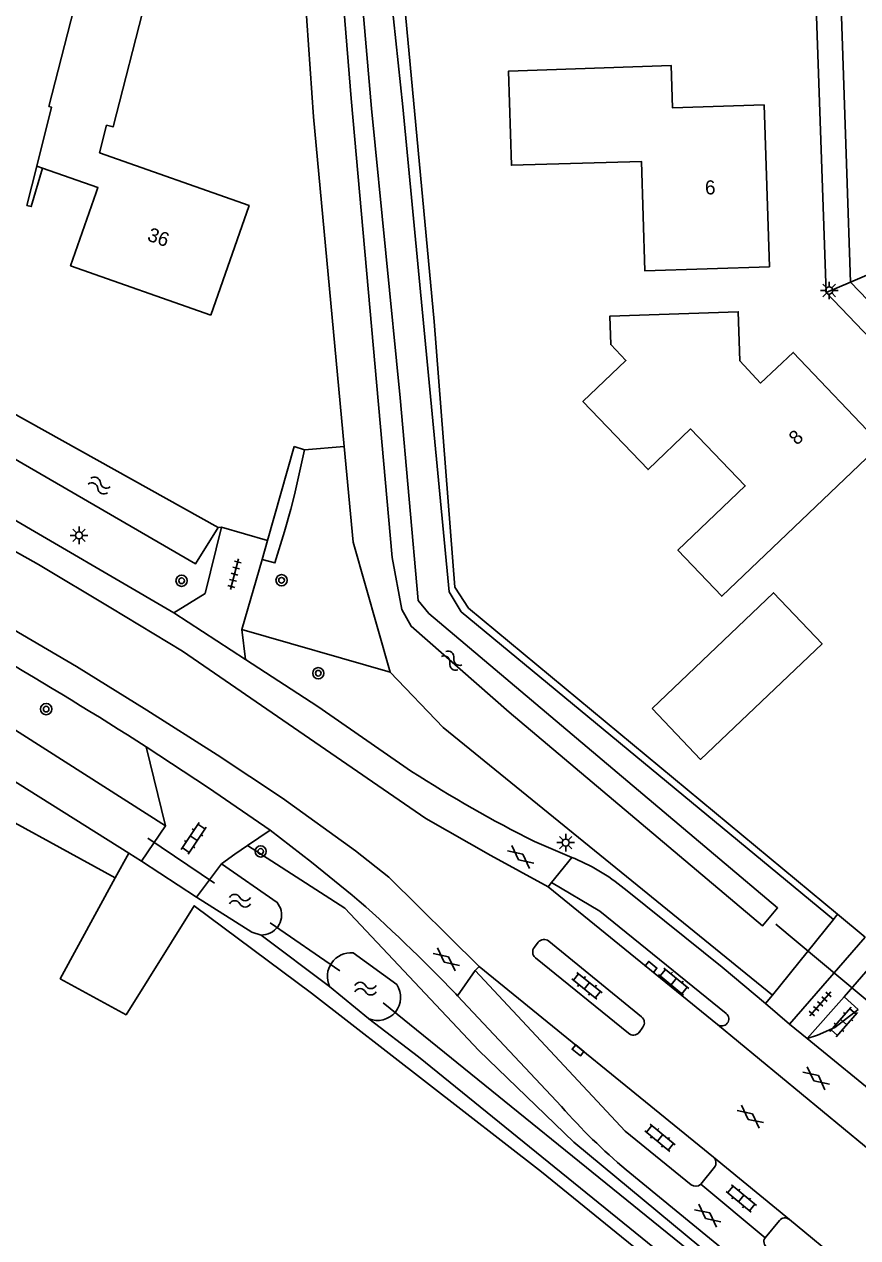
# Model space of a CAD drawing. Extents: x 136000 to 141014, y 402000 to 403500.
# Drawn here: x 137059.9 to 137119.1, y 402057.2 to 402143.4 of the extents above; entities that cross this region are included whole.
import ezdxf

# ---------------------------------------------------------------- set-up
doc = ezdxf.new("R2010")
doc.units = 0
for name, color, linetype in [('gg-afsc-erfafscheiding', 7, 'Continuous'), ('gg-afsc-muur', 7, 'Continuous'), ('gg-anno-huisnummerreeks BGT', 7, 'Continuous'), ('gg-bbg-bijgebouw', 7, 'Continuous'), ('gg-bbg-gedigitaliseerde bebouwing', 7, 'Continuous'), ('gg-bbg-hoofdgebouw', 7, 'Continuous'), ('gg-knt-bronhoudergrens', 7, 'Continuous'), ('gg-knt-verharding', 7, 'Continuous'), ('gg-knt-verharding nz', 7, 'Continuous'), ('gg-kntw-bovenkant insteek waterloop', 7, 'Continuous'), ('gg-kntw-waterlijn', 7, 'Continuous'), ('gg-kwrk-duiker nz buis', 7, 'Continuous'), ('gt-grn-groengrens', 7, 'Continuous'), ('gt-grn-groengrens NZ', 7, 'Continuous'), ('gt-grn-vlakafsluiter', 7, 'Continuous'), ('gt-grn-weggrens', 7, 'Continuous'), ('gt-symb-boom', 7, 'Continuous'), ('gt-symb-gesloten verharding', 7, 'Continuous'), ('gt-symb-klinker verharding', 7, 'Continuous'), ('gt-symb-kolk', 7, 'Continuous'), ('gt-symb-lichtmast', 7, 'Continuous'), ('gt-symb-tegel verharding', 7, 'Continuous'), ('gt-symb-watersymbool', 7, 'Continuous')]:
    doc.layers.add(name, color=color, linetype=linetype)

# ---------------------------------------------------------------- blocks, each defined once
blk = doc.blocks.new('gt0-KL1')
at = {"layer": 'gt-symb-klinker verharding'}
for p, q in [((-1.15, 0.3), (1.15, 0.3)), ((-1, -0.3), (-1, 0.3)), ((-0.5, 0.3), (-0.5, 0.45)), ((0, -0.3), (0, 0.3)), ((0.5, 0.3), (0.5, 0.45)), ((1, -0.3), (1, 0.3)), ((-1.15, -0.3), (1.15, -0.3)), ((-0.5, -0.45), (-0.5, -0.3)), ((0.5, -0.45), (0.5, -0.3))]:
    blk.add_line(p, q, dxfattribs=at)
blk = doc.blocks.new('gt0-KOLK')
at = {"layer": 'gt-symb-kolk'}
blk.add_lwpolyline([(0, 0), (0.375, 0), (0.375, 0.4), (-0.375, 0.4), (-0.375, 0), (0, 0)], dxfattribs=at)
blk = doc.blocks.new('gt0-LMAST')
at = {"layer": 'gt-symb-lichtmast'}
for p, q in [((-0.182, 0.173), (-0.447, 0.438)), ((-0.005, 0.246), (-0.005, 0.621)), ((0.172, 0.173), (0.437, 0.438)), ((-0.255, -0.004), (-0.63, -0.004)), ((-0.182, -0.181), (-0.447, -0.446)), ((-0.005, -0.254), (-0.005, -0.629)), ((0.437, -0.446), (0.172, -0.181)), ((0.245, -0.004), (0.62, -0.004))]:
    blk.add_line(p, q, dxfattribs=at)
blk.add_circle((-0.005, -0.004), 0.25, dxfattribs=at)
blk = doc.blocks.new('gt0-TEG1')
at = {"layer": 'gt-symb-tegel verharding'}
for p, q in [((-1.125, 0), (1.125, 0)), ((-0.9, -0.25), (-0.9, 0.25)), ((-0.45, -0.25), (-0.45, 0.25)), ((0, -0.25), (0, 0.25)), ((0.45, -0.25), (0.45, 0.25)), ((0.9, -0.25), (0.9, 0.25))]:
    blk.add_line(p, q, dxfattribs=at)
blk = doc.blocks.new('gt0-BOOM')
at = {"layer": 'gt-symb-boom'}
for radius in [0.4, 0.2]:
    blk.add_circle((0, 0), radius, dxfattribs=at)
blk = doc.blocks.new('gt0-WA')
at = {"layer": 'gt-symb-watersymbool'}
for centre, start, end in [((-0.323, 0.022), 28.07249, 151.92751), ((0.427, 0.422), 208.07248, 331.92751), ((-0.323, -0.428), 28.07249, 151.92751), ((0.427, -0.028), 208.07248, 331.92751)]:
    blk.add_arc(centre, 0.425, start, end, dxfattribs=at)
blk = doc.blocks.new('gt0-GESVH1')
at = {"layer": 'gt-symb-gesloten verharding'}
for p, q in [((-0.992, -0.261), (0.008, 0.239)), ((0.008, -0.261), (-0.992, 0.239)), ((0.008, 0.239), (1.008, -0.261)), ((1.008, 0.239), (0.008, -0.261))]:
    blk.add_line(p, q, dxfattribs=at)

msp = doc.modelspace()

# ---------------------------------------------------------------- linework, layer by layer
at = {"layer": 'gg-afsc-erfafscheiding'}
msp.add_line((137072.1, 402081.41), (137068.194, 402083.954), dxfattribs=at)
at = {"layer": 'gg-afsc-muur'}
msp.add_lwpolyline([(137060.741, 402133.32), (137060.044, 402130.545), (137060.348, 402130.457), (137061.137, 402133.182)], dxfattribs=at)
at = {"layer": 'gg-bbg-bijgebouw'}
msp.add_lwpolyline([(137104.457, 402094.809), (137107.903, 402091.187), (137116.545, 402099.408), (137113.098, 402103.03), (137104.457, 402094.809)], dxfattribs=at)
at = {"layer": 'gg-bbg-gedigitaliseerde bebouwing'}
msp.add_lwpolyline([(137073.1, 402122.75), (137075.828, 402130.525), (137065.203, 402134.277), (137065.704, 402136.235), (137066.164, 402136.117), (137068.455, 402145.062), (137063.823, 402146.248), (137061.598, 402137.561)], dxfattribs=at)
at = {"layer": 'gg-bbg-hoofdgebouw'}
msp.add_line((137061.137, 402133.182), (137060.741, 402133.32), dxfattribs=at)
for points in [[(137112.793, 402126.178), (137103.944, 402125.897), (137103.708, 402133.672), (137094.469, 402133.391), (137094.27, 402140.082), (137105.824, 402140.469), (137105.922, 402137.47), (137112.418, 402137.684), (137112.793, 402126.178)], [(137061.598, 402137.561), (137061.793, 402137.512), (137060.741, 402133.32)], [(137061.137, 402133.182), (137065.088, 402131.808), (137064.964, 402131.452)], [(137073.1, 402122.75), (137063.14, 402126.25), (137064.964, 402131.452)], [(137120.71, 402113.567), (137114.495, 402120.096), (137112.169, 402117.924), (137110.7, 402119.498), (137110.58, 402122.986), (137101.46, 402122.685), (137101.524, 402120.656), (137102.597, 402119.529), (137099.547, 402116.614), (137104.172, 402111.774), (137107.2, 402114.668), (137111.078, 402110.611), (137106.296, 402106.041), (137109.412, 402102.781), (137120.71, 402113.567)]]:
    msp.add_lwpolyline(points, dxfattribs=at)
at = {"layer": 'gg-knt-bronhoudergrens'}
msp.add_line((137066.322, 402082.767), (137067.284, 402084.525), dxfattribs=at)
for points in [[(137031.735, 402101.682), (137055.221, 402088.838), (137066.322, 402082.767)], [(137066.322, 402082.767), (137062.407, 402075.608), (137067.085, 402073.05), (137071.929, 402080.799), (137080.27, 402074.591), (137096.604, 402061.892), (137120.347, 402042.619), (137142.522, 402024.619), (137156.112, 402013.588)]]:
    msp.add_lwpolyline(points, dxfattribs=at)
at = {"layer": 'gg-knt-verharding'}
for p, q in [((137115.112, 402175.269), (137116.194, 402142.603)), ((137116.834, 402124.346), (137116.194, 402142.603)), ((137138.099, 402102.093), (137116.834, 402124.346)), ((137077.134, 402106.748), (137079.028, 402113.41)), ((137055.253, 402110.477), (137070.475, 402101.603)), ((137073.869, 402107.676), (137077.134, 402106.748)), ((137076.745, 402105.38), (137077.134, 402106.748)), ((137076.745, 402105.38), (137075.313, 402100.422)), ((137075.565, 402098.277), (137070.475, 402101.603)), ((137140.928, 402100.63), (137118.098, 402074.332)), ((137075.313, 402100.422), (137075.565, 402098.277)), ((137069.883, 402086.481), (137068.503, 402092.08)), ((137077.316, 402086.156), (137075.717, 402085.07)), ((137096.108, 402085.347), (137098.751, 402084.231)), ((137098.751, 402084.231), (137098.965, 402084.141)), ((137097.318, 402082.452), (137097.066, 402082.135)), ((137097.066, 402082.135), (137109.101, 402072.366)), ((137096.099, 402077.849), (137096.373, 402078.205)), ((137097.117, 402078.287), (137103.715, 402072.901)), ((137119.598, 402078.571), (137114.237, 402072.392)), ((137092.179, 402076.49), (137091.881, 402076.184)), ((137108.821, 402062.944), (137092.179, 402076.49)), ((137102.786, 402071.734), (137096.168, 402077.105)), ((137090.638, 402074.401), (137090.519, 402074.528)), ((137098.028, 402066.527), (137090.638, 402074.401)), ((137112.511, 402073.846), (137114.237, 402072.392)), ((137115.482, 402071.362), (137118.098, 402074.332)), ((137118.098, 402074.332), (137119.109, 402073.428)), ((137103.808, 402072.163), (137103.536, 402071.803)), ((137109.101, 402072.366), (137123.63, 402060.371)), ((137114.237, 402072.392), (137115.482, 402071.362)), ((137115.482, 402071.362), (137121.543, 402066.393)), ((137108.821, 402062.944), (137114.219, 402058.512)), ((137115.5, 402051.483), (137102.613, 402062.042)), ((137107.915, 402061.015), (137108.905, 402062.218)), ((137112.487, 402057.213), (137107.915, 402061.015)), ((137113.516, 402058.446), (137112.487, 402057.213)), ((137130.8, 402044.838), (137114.219, 402058.512))]:
    msp.add_line(p, q, dxfattribs=at)
for points in [[(137070.475, 402101.603), (137072.701, 402102.979), (137073.869, 402107.676)], [(137075.565, 402098.277), (137080.723, 402094.955), (137087.369, 402090.332)], [(137077.316, 402086.156), (137072.939, 402089.162), (137068.503, 402092.08)], [(137083.162, 402081.551), (137080.262, 402083.883), (137077.316, 402086.156)], [(137075.717, 402085.07), (137074.805, 402084.451), (137073.878, 402083.778)], [(137097.318, 402082.452), (137100.75, 402080.415), (137109.728, 402073.146)], [(137102.697, 402081.847), (137109.446, 402076.427), (137112.511, 402073.846)], [(137091.881, 402076.184), (137102.559, 402064.78), (137107.227, 402060.976)]]:
    msp.add_lwpolyline(points, dxfattribs=at)
for centre, radius, start, end in [((136923.585, 401866.961), 267.731, 57.22892, 62.60105), ((137139.821, 402172.131), 97.171, 237.33076, 243.26565), ((137093.37, 402070.856), 14.415, 49.6816, 67.16166), ((137008.924, 401996.418), 112.955, 43.75011, 48.91099), ((137096.789, 402077.843), 0.552, 53.60925, 138.96969), ((137096.503, 402077.511), 0.527, 140.12386, 230.47327), ((137103.374, 402072.483), 0.539, 323.5589, 50.80578), ((137109.414, 402072.756), 0.5, 231.28662, 51.12552), ((137103.127, 402072.134), 0.526, 229.49155, 321.02128), ((137130.735, 402095.377), 43.613, 221.41485, 229.84851), ((137108.426, 402062.53), 0.572, 326.88571, 46.31412), ((137107.549, 402061.392), 0.525, 232.26644, 314.22236), ((137113.902, 402058.112), 0.511, 51.61479, 139.11201), ((137112.865, 402056.947), 0.462, 144.80281, 242.75134)]:
    msp.add_arc(centre, radius, start, end, dxfattribs=at)
at = {"layer": 'gg-knt-verharding nz'}
for p, q in [((137116.373, 402190.816), (137118.295, 402132.805)), ((137118.557, 402125.097), (137118.295, 402132.805)), ((137139.381, 402103.29), (137118.557, 402125.097))]:
    msp.add_line(p, q, dxfattribs=at)
for points in [[(137097.066, 402082.135), (137092.995, 402084.357), (137088.379, 402086.999), (137071.101, 402098.883), (137066.007, 402101.968), (137060.875, 402105.046), (137055.665, 402107.95), (137050.439, 402110.718), (137045.082, 402113.527), (137039.711, 402116.175), (137034.31, 402118.696), (137028.848, 402121.106), (137023.353, 402123.566), (137017.776, 402125.868), (137012.197, 402128.034), (137006.579, 402130.096), (137000.948, 402131.975), (136995.13, 402133.791), (136988.319, 402135.892), (136981.107, 402138.306)], [(136979.307, 402130.822), (136984.991, 402129.932), (136990.74, 402128.77), (136996.608, 402127.506), (137002.43, 402126.095), (137008.065, 402124.337), (137013.737, 402122.302), (137019.174, 402119.966), (137031.98, 402114.287), (137037.355, 402111.802), (137042.716, 402109.155), (137053.239, 402103.703), (137058.359, 402100.844), (137063.569, 402097.781), (137068.573, 402094.689), (137073.558, 402091.505), (137078.199, 402088.443), (137083.387, 402084.706), (137085.753, 402082.83), (137092.179, 402076.49)]]:
    msp.add_lwpolyline(points, dxfattribs=at)
at = {"layer": 'gg-kntw-bovenkant insteek waterloop'}
for p, q in [((137079.409, 402151.337), (137080.4, 402136.83)), ((137085.209, 402152.148), (137086.76, 402137.54)), ((137080.4, 402136.83), (137082.584, 402113.423)), ((137058.856, 402115.897), (137073.636, 402107.672)), ((137068.194, 402083.954), (137069.883, 402086.481)), ((137067.284, 402084.525), (137068.194, 402083.954)), ((137073.878, 402083.778), (137072.1, 402081.41)), ((137113.02, 402074.45), (137117.34, 402079.81)), ((137086.319, 402075.19), (137083.217, 402077.455))]:
    msp.add_line(p, q, dxfattribs=at)
for points in [[(137117.34, 402079.81), (137090.89, 402101.68), (137090.05, 402103.1), (137086.76, 402137.54)], [(137073.636, 402107.672), (137072.013, 402105.075), (137057.551, 402113.456), (137058.856, 402115.897)], [(137082.584, 402113.423), (137083.22, 402106.61), (137085.841, 402097.39)], [(137069.883, 402086.481), (137058.384, 402093.814), (137041.17, 402103.49), (137023.613, 402111.466), (137022.278, 402112.072)], [(137023.899, 402106.927), (137029.526, 402104.37), (137040.551, 402099.658), (137057.057, 402090.945), (137067.284, 402084.525)], [(137085.841, 402097.39), (137089.61, 402093.45), (137113.02, 402074.45)], [(137073.878, 402083.778), (137077.828, 402081.027), (137078.056, 402080.615)], [(137076.677, 402078.715), (137076.014, 402078.912), (137072.1, 402081.41)], [(137081.543, 402075.065), (137084.3, 402072.782), (137084.331, 402072.759)]]:
    msp.add_lwpolyline(points, dxfattribs=at)
for centre, radius, start, end in [((137076.708, 402080.143), 1.428, 268.75118, 19.30532), ((137083.081, 402075.769), 1.691, 85.37402, 204.60977), ((137084.946, 402074.285), 1.645, 248.05002, 33.39941)]:
    msp.add_arc(centre, radius, start, end, dxfattribs=at)
at = {"layer": 'gg-kntw-waterlijn'}
msp.add_lwpolyline([(137081.452, 402158.294), (137083.091, 402138.143), (137085.99, 402105.527), (137086.686, 402101.832), (137087.34, 402100.645), (137094.313, 402094.549), (137112.303, 402079.361), (137113.379, 402080.636), (137109.283, 402084.094), (137088.588, 402101.565), (137087.84, 402102.467), (137086.563, 402116.868), (137084.533, 402137.416), (137083.093, 402153.886)], dxfattribs=at)
at = {"layer": 'gg-kwrk-duiker nz buis'}
for p, q in [((137068.625, 402085.6), (137073.378, 402082.404)), ((137082.279, 402076.18), (137077.332, 402079.577)), ((137113.261, 402079.482), (137130.188, 402065.331)), ((137129.302, 402038.36), (137085.346, 402073.899))]:
    msp.add_line(p, q, dxfattribs=at)
at = {"layer": 'gt-grn-groengrens'}
for p, q in [((137079.756, 402113.182), (137079.028, 402113.41)), ((137073.636, 402107.672), (137073.869, 402107.676)), ((137075.313, 402100.422), (137085.841, 402097.39)), ((137117.646, 402080.189), (137117.34, 402079.81)), ((137119.598, 402078.571), (137117.646, 402080.189)), ((137076.677, 402078.715), (137081.543, 402075.065)), ((137112.511, 402073.846), (137113.02, 402074.45))]:
    msp.add_line(p, q, dxfattribs=at)
for points in [[(137117.646, 402080.189), (137091.407, 402101.943), (137090.442, 402103.42), (137088.984, 402122.291), (137085.73, 402157.066), (137084.202, 402173.04)], [(137076.745, 402105.38), (137077.663, 402105.145), (137078.339, 402107.371), (137078.79, 402108.963), (137079.054, 402109.99), (137079.756, 402113.182)], [(137128.405, 402037.207), (137087.861, 402070.056), (137084.331, 402072.759)]]:
    msp.add_lwpolyline(points, dxfattribs=at)
at = {"layer": 'gt-grn-groengrens NZ'}
msp.add_lwpolyline([(137075.717, 402085.07), (137082.624, 402080.619), (137092.162, 402070.505), (137098.905, 402064.009), (137115.843, 402049.949), (137122.257, 402045.837), (137135.495, 402038.108), (137146.969, 402029.217)], dxfattribs=at)
at = {"layer": 'gt-grn-vlakafsluiter'}
msp.add_line((137082.584, 402113.423), (137079.756, 402113.182), dxfattribs=at)
at = {"layer": 'gt-grn-weggrens'}
for p, q in [((137118.557, 402125.097), (137122.981, 402126.982)), ((137116.834, 402124.346), (137118.557, 402125.097)), ((137097.318, 402082.452), (137098.751, 402084.231)), ((137091.881, 402076.184), (137090.638, 402074.401))]:
    msp.add_line(p, q, dxfattribs=at)
msp.add_lwpolyline([(137119.109, 402073.428), (137117.456, 402072.138), (137116.225, 402071.6), (137115.482, 402071.362)], dxfattribs=at)

# ---------------------------------------------------------------- block references
at = {"layer": 'gt-symb-boom'}
for p in [(137071.033, 402103.881), (137080.745, 402097.313), (137061.41, 402094.764), (137076.65, 402084.654)]:
    msp.add_blockref('gt0-BOOM', p, dxfattribs=at)
at = {"layer": 'gt-symb-boom', "rotation": -46.29643001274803}
msp.add_blockref('gt0-BOOM', (137078.133, 402103.915), dxfattribs=at)
at = {"layer": 'gt-symb-gesloten verharding'}
for p, rotation in [((137095.128, 402084.272), -38.54346271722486), ((137089.849, 402076.992), -38.54346272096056), ((137116.119, 402068.559), -38.543462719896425), ((137111.448, 402065.829), -38.543462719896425), ((137108.414, 402058.791), -38.543462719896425)]:
    msp.add_blockref('gt0-GESVH1', p, dxfattribs=dict(at, rotation=rotation))
at = {"layer": 'gt-symb-klinker verharding'}
for p, rotation in [((137071.888, 402085.586), 56.13505688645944), ((137106, 402075.409), -39.48286402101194), ((137099.834, 402075.107), -38.8298249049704), ((137118.068, 402072.534), 48.72788342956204), ((137105.029, 402064.307), -39.482864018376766), ((137110.793, 402060), -39.48286402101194)]:
    msp.add_blockref('gt0-KL1', p, dxfattribs=dict(at, rotation=rotation))
at = {"layer": 'gt-symb-kolk'}
for p, rotation in [((137104.266, 402076.297), -39.03551289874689), ((137099.325, 402070.676), 140.84774132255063)]:
    msp.add_blockref('gt0-KOLK', p, dxfattribs=dict(at, rotation=rotation))
at = {"layer": 'gt-symb-lichtmast'}
for p in [(137117.052, 402124.503), (137063.747, 402107.106), (137098.327, 402085.285)]:
    msp.add_blockref('gt0-LMAST', p, dxfattribs=at)
at = {"layer": 'gt-symb-tegel verharding'}
for p, rotation in [((137074.794, 402104.345), 75.2272760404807), ((137116.414, 402073.822), 48.93264367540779)]:
    msp.add_blockref('gt0-TEG1', p, dxfattribs=dict(at, rotation=rotation))
at = {"layer": 'gt-symb-watersymbool'}
for p, rotation in [((137065.123, 402110.669), -24.003190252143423), ((137090.193, 402098.24), -39.563508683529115)]:
    msp.add_blockref('gt0-WA', p, dxfattribs=dict(at, rotation=rotation))
for p in [(137075.125, 402081.157), (137084.043, 402074.908)]:
    msp.add_blockref('gt0-WA', p, dxfattribs=at)

# ---------------------------------------------------------------- texts
at = {"layer": 'gg-anno-huisnummerreeks BGT'}
for s, rotation, p in [('6', 1.9, (137108.236, 402131.31)), ('36', 340.6, (137068.53, 402128.066)), ('8', 43.6, (137114.754, 402113.46))]:
    msp.add_text(s, height=1, rotation=rotation, dxfattribs=at).set_placement(p)

doc.saveas('drawing.dxf')
